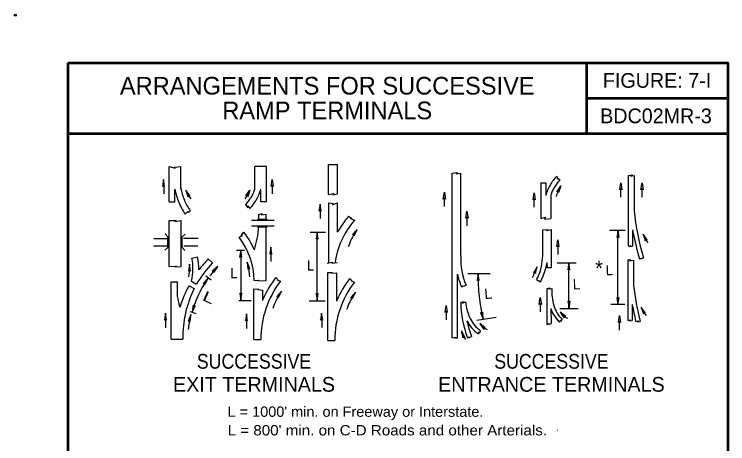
# Model space of a CAD drawing. Extents: x -5.247 to -4.572, y 0.948 to 1.832.
# Drawn here: x -5.247 to -4.616, y 1.452 to 1.832 of the extents above; entities that cross this region are included whole.
import ezdxf
from ezdxf.enums import TextEntityAlignment as Align

# ---------------------------------------------------------------- set-up
doc = ezdxf.new("R2010")
doc.units = 0
doc.header["$LTSCALE"] = 0.0036
doc.header["$PDMODE"] = 32
doc.header["$PDSIZE"] = 0.0018
doc.linetypes.add('LONG_DASHED', pattern=[7.5, 6, -1.5])
doc.linetypes.add('MEDIUM_DASHED', pattern=[4.5, 3, -1.5])
doc.layers.add('1', color=7, linetype='Continuous', lineweight=25)

msp = doc.modelspace()

# ---------------------------------------------------------------- linework, layer by layer
at = {"layer": '1', "lineweight": 53}
for p, q in [((-4.740967, 1.789417), (-4.740967, 1.726917)), ((-4.740967, 1.758167), (-4.615967, 1.758167)), ((-5.1993, 1.726917), (-4.615967, 1.726917))]:
    msp.add_line(p, q, dxfattribs=at)
at = {"layer": '1', "linetype": 'LONG_DASHED'}
for p, q in [((-5.109917, 1.6663), (-5.109917, 1.697758)), ((-5.0995, 1.677425), (-5.0995, 1.697758)), ((-5.023775, 1.697758), (-5.034192, 1.697758)), ((-5.034192, 1.677425), (-5.034192, 1.697758)), ((-5.023775, 1.6663), (-5.023775, 1.697758)), ((-4.781175, 1.683183), (-4.781175, 1.651717)), ((-4.77255, 1.67205), (-4.77255, 1.651717))]:
    msp.add_line(p, q, dxfattribs=at)
at = {"layer": '1'}
for p, q in [((-4.96895, 1.699517), (-4.961067, 1.699517)), ((-4.96895, 1.672733), (-4.96895, 1.699517)), ((-4.961067, 1.673467), (-4.961067, 1.699517)), ((-4.859692, 1.545942), (-4.859692, 1.691775)), ((-4.851883, 1.618633), (-4.851883, 1.691775)), ((-4.704025, 1.689708), (-4.704025, 1.627208)), ((-4.698817, 1.689708), (-4.698817, 1.658458)), ((-5.114783, 1.680583), (-5.114783, 1.673317)), ((-5.018908, 1.680583), (-5.018908, 1.673317)), ((-4.710683, 1.677708), (-4.710683, 1.670442)), ((-4.691875, 1.677708), (-4.691875, 1.670442)), ((-4.866667, 1.669475), (-4.866667, 1.662217)), ((-4.787308, 1.668892), (-4.787308, 1.661633)), ((-4.968658, 1.611975), (-4.968658, 1.665317)), ((-4.961067, 1.639592), (-4.961067, 1.665317)), ((-5.030667, 1.651042), (-5.030708, 1.655192)), ((-5.024275, 1.651025), (-5.024275, 1.655525)), ((-4.976425, 1.658767), (-4.976425, 1.651508)), ((-5.109833, 1.609142), (-5.109833, 1.649858)), ((-5.099417, 1.609142), (-5.099417, 1.649858)), ((-5.037125, 1.650017), (-5.017192, 1.650017)), ((-5.031717, 1.651025), (-5.023283, 1.651025)), ((-4.846675, 1.652425), (-4.846675, 1.645167)), ((-5.037125, 1.645175), (-5.017192, 1.645175)), ((-5.031717, 1.644167), (-5.023283, 1.644167)), ((-5.024275, 1.596758), (-5.024275, 1.644167)), ((-4.779442, 1.623042), (-4.779417, 1.64155)), ((-4.706758, 1.641092), (-4.720592, 1.641092)), ((-4.700208, 1.641483), (-4.700208, 1.627208)), ((-5.111, 1.6353), (-5.11345, 1.638)), ((-5.111, 1.625925), (-5.111, 1.6353)), ((-4.985217, 1.639442), (-4.971567, 1.639442)), ((-5.1137, 1.623475), (-5.111, 1.625925)), ((-5.09595, 1.623225), (-5.0984, 1.625925)), ((-5.050425, 1.623642), (-5.04345, 1.623642)), ((-4.766333, 1.627142), (-4.766333, 1.619883)), ((-5.089842, 1.616608), (-5.084742, 1.61765)), ((-5.075292, 1.615917), (-5.07155, 1.612292)), ((-5.020025, 1.620675), (-5.020025, 1.613417)), ((-4.766767, 1.612333), (-4.749917, 1.612333)), ((-4.704425, 1.615042), (-4.704425, 1.56135)), ((-4.699217, 1.614642), (-4.699217, 1.5926)), ((-4.969592, 1.543667), (-4.969592, 1.603667)), ((-4.961792, 1.5783), (-4.961792, 1.603517)), ((-4.845858, 1.6029), (-4.825942, 1.6029)), ((-5.077408, 1.6008), (-5.07275, 1.597225)), ((-4.8549, 1.545942), (-4.8549, 1.601925)), ((-4.784958, 1.597483), (-4.781558, 1.595683)), ((-5.108208, 1.544917), (-5.108208, 1.5956)), ((-5.092333, 1.592042), (-5.08775, 1.589567)), ((-5.090067, 1.59625), (-5.085633, 1.5935)), ((-5.034983, 1.544525), (-5.034983, 1.589483)), ((-5.027175, 1.579167), (-5.027175, 1.588317)), ((-4.775875, 1.589642), (-4.775925, 1.5579)), ((-5.048383, 1.579167), (-5.037342, 1.579167)), ((-4.986092, 1.578683), (-4.971858, 1.578683)), ((-4.781808, 1.576175), (-4.781808, 1.568917)), ((-4.772542, 1.572067), (-4.772542, 1.572058)), ((-4.772525, 1.571883), (-4.772108, 1.558667)), ((-4.764417, 1.571958), (-4.74835, 1.571958)), ((-4.706958, 1.575433), (-4.719317, 1.575433)), ((-4.7006, 1.575633), (-4.7006, 1.56135)), ((-5.091483, 1.569392), (-5.0864, 1.56755)), ((-4.865092, 1.569125), (-4.865092, 1.561858)), ((-5.113033, 1.56225), (-5.113033, 1.554983)), ((-5.041533, 1.561667), (-5.041533, 1.5544)), ((-4.974983, 1.562392), (-4.974983, 1.555133)), ((-4.837858, 1.561767), (-4.820717, 1.564383)), ((-4.775817, 1.557858), (-4.774217, 1.55865)), ((-4.774267, 1.558725), (-4.774267, 1.557833)), ((-4.774225, 1.557817), (-4.772108, 1.558667)), ((-4.711858, 1.5601), (-4.711858, 1.552842)), ((-5.108208, 1.544917), (-5.097792, 1.544917)), ((-5.034983, 1.544525), (-5.028775, 1.544525)), ((-4.969592, 1.543667), (-4.963383, 1.543667))]:
    msp.add_line(p, q, dxfattribs=at)
at = {"layer": '1', "linetype": 'MEDIUM_DASHED'}
for p, q in [((-4.713025, 1.575433), (-4.713025, 1.640817)), ((-4.978983, 1.578683), (-4.978983, 1.639442)), ((-5.123583, 1.633842), (-5.111567, 1.633842)), ((-5.097275, 1.63405), (-5.0844, 1.63405)), ((-5.1238, 1.627558), (-5.111792, 1.627558)), ((-5.097042, 1.627558), (-5.084617, 1.627558)), ((-5.04665, 1.623642), (-5.0465, 1.57975)), ((-4.756583, 1.571758), (-4.756583, 1.612233))]:
    msp.add_line(p, q, dxfattribs=at)
at = {"layer": '1', "lineweight": 53}
msp.add_lwpolyline([(-5.1993, 1.789417), (-4.615967, 1.789417), (-4.615967, 0.99775), (-5.1993, 0.99775)], close=True, dxfattribs=at)
at = {"layer": '1', "linetype": 'LONG_DASHED'}
for points in [[(-5.109917, 1.697758), (-5.104567, 1.69625), (-5.105, 1.696975), (-5.0995, 1.697758)], [(-4.781175, 1.683183), (-4.776917, 1.683233), (-4.776917, 1.67205)], [(-5.109917, 1.6663), (-5.1048, 1.666233), (-5.1048, 1.677425)], [(-5.023775, 1.6663), (-5.028883, 1.666233), (-5.028883, 1.677425)]]:
    msp.add_lwpolyline(points, dxfattribs=at)
at = {"layer": '1'}
for points in [[(-4.859692, 1.691775), (-4.855017, 1.692417), (-4.856025, 1.6911), (-4.851883, 1.691775)], [(-4.767183, 1.68905), (-4.766425, 1.686425), (-4.766083, 1.687317), (-4.764292, 1.685917)], [(-4.704025, 1.689708), (-4.700292, 1.690208), (-4.701975, 1.688967), (-4.698817, 1.689708)], [(-4.96895, 1.672733), (-4.964608, 1.673733), (-4.965283, 1.672675), (-4.961067, 1.673467)], [(-5.042292, 1.663958), (-5.04045, 1.66105), (-5.04045, 1.66285), (-5.038617, 1.660425)], [(-4.968658, 1.665317), (-4.964583, 1.664733), (-4.965458, 1.663567), (-4.961067, 1.665317)], [(-5.0957, 1.6554), (-5.0935, 1.657667), (-5.0935, 1.656767), (-5.091317, 1.658417)], [(-5.030708, 1.655192), (-5.027567, 1.655983), (-5.028458, 1.654858), (-5.024275, 1.655525)], [(-4.9512, 1.65365), (-4.948342, 1.651458), (-4.949533, 1.651675), (-4.946042, 1.650025)], [(-5.109833, 1.649858), (-5.103617, 1.649733), (-5.104775, 1.649008), (-5.099417, 1.649858)], [(-4.781175, 1.651717), (-4.777108, 1.652758), (-4.778017, 1.651067), (-4.77255, 1.651717)], [(-4.779417, 1.64155), (-4.775425, 1.641725), (-4.7761, 1.640933), (-4.771967, 1.641942)], [(-4.771967, 1.641942), (-4.771967, 1.607833), (-4.7753, 1.607842), (-4.775683, 1.61255)], [(-5.0984, 1.625925), (-5.0984, 1.6353), (-5.0957, 1.63775)], [(-5.048025, 1.634975), (-5.04505, 1.63665), (-5.046358, 1.636508), (-5.043842, 1.639467)], [(-4.704025, 1.627208), (-4.701683, 1.627667), (-4.702525, 1.626875), (-4.700208, 1.627208)], [(-4.693942, 1.615808), (-4.692292, 1.616633), (-4.692733, 1.616008), (-4.690483, 1.6169)], [(-5.109833, 1.609142), (-5.10375, 1.609475), (-5.104917, 1.60875), (-5.099417, 1.609142)], [(-4.970217, 1.611975), (-4.965717, 1.61285), (-4.966158, 1.612125), (-4.961067, 1.612558)], [(-4.704425, 1.615042), (-4.701517, 1.614883), (-4.702858, 1.614267), (-4.699217, 1.614642)], [(-4.969592, 1.603667), (-4.965575, 1.603842), (-4.966008, 1.603108), (-4.961792, 1.603517)], [(-5.034692, 1.596758), (-5.030667, 1.597042), (-5.03125, 1.596458), (-5.024275, 1.596758)], [(-5.015708, 1.599383), (-5.013742, 1.59755), (-5.014383, 1.5974), (-5.011483, 1.596175)], [(-4.950325, 1.598517), (-4.948358, 1.596683), (-4.949, 1.596542), (-4.946092, 1.595308)], [(-5.108208, 1.5956), (-5.102908, 1.5956), (-5.102908, 1.584667)], [(-4.851375, 1.59115), (-4.84985, 1.592108), (-4.849775, 1.591675), (-4.84735, 1.592683)], [(-4.775875, 1.589642), (-4.773217, 1.590133), (-4.774275, 1.588967), (-4.771542, 1.589567)], [(-5.034983, 1.589483), (-5.03095, 1.589192), (-5.031675, 1.588758), (-5.027175, 1.588317)], [(-4.852108, 1.577175), (-4.849633, 1.57805), (-4.850508, 1.576733), (-4.847892, 1.577758)], [(-4.764633, 1.559775), (-4.763625, 1.561525), (-4.76365, 1.560358), (-4.76225, 1.5623)], [(-4.704425, 1.56135), (-4.701933, 1.561792), (-4.702892, 1.561108), (-4.7006, 1.56135)], [(-4.697225, 1.560558), (-4.694958, 1.560942), (-4.695858, 1.560217), (-4.693433, 1.560333)], [(-4.836417, 1.549417), (-4.835683, 1.5513), (-4.835542, 1.550142), (-4.834458, 1.552275)], [(-4.859692, 1.545942), (-4.85705, 1.54665), (-4.857633, 1.545925), (-4.8549, 1.545942)], [(-4.84615, 1.545925), (-4.844692, 1.546942), (-4.84455, 1.546067), (-4.84265, 1.547192)]]:
    msp.add_lwpolyline(points, dxfattribs=at)
for points in [[(-5.1158, 1.679933), (-5.114875, 1.681058), (-5.113958, 1.679933), (-5.114875, 1.6861)], [(-5.017883, 1.679933), (-5.018817, 1.681058), (-5.019733, 1.679933), (-5.018817, 1.6861)], [(-4.765483, 1.674508), (-4.765817, 1.675925), (-4.767133, 1.675317), (-4.763592, 1.680442)], [(-4.709667, 1.677058), (-4.710592, 1.678183), (-4.711508, 1.677058), (-4.710592, 1.683225)], [(-4.69085, 1.677058), (-4.691775, 1.678183), (-4.692692, 1.677058), (-4.691775, 1.683225)], [(-5.093292, 1.670708), (-5.092958, 1.672125), (-5.09165, 1.671517), (-5.095192, 1.676642)], [(-5.0404, 1.670708), (-5.040733, 1.672125), (-5.042042, 1.671517), (-5.0385, 1.676642)], [(-4.865642, 1.668833), (-4.866567, 1.669958), (-4.867483, 1.668833), (-4.866567, 1.675)], [(-4.786292, 1.66825), (-4.787217, 1.669375), (-4.788133, 1.66825), (-4.787217, 1.674417)], [(-4.97745, 1.658125), (-4.976525, 1.65925), (-4.975608, 1.658125), (-4.976525, 1.664292)], [(-4.84565, 1.651775), (-4.846583, 1.6529), (-4.8475, 1.651775), (-4.846583, 1.657942)], [(-4.947825, 1.637342), (-4.94645, 1.637775), (-4.946283, 1.636333), (-4.943708, 1.642008)], [(-4.713892, 1.634808), (-4.712967, 1.635933), (-4.71205, 1.634808), (-4.712967, 1.640975)], [(-4.980042, 1.633258), (-4.979117, 1.634383), (-4.9782, 1.633258), (-4.979117, 1.639425)], [(-4.688983, 1.631892), (-4.68865, 1.633308), (-4.687342, 1.632708), (-4.690883, 1.637833)], [(-4.765308, 1.6265), (-4.766233, 1.627625), (-4.76715, 1.6265), (-4.766233, 1.632667)], [(-5.047617, 1.617267), (-5.046692, 1.618392), (-5.045775, 1.617267), (-5.046692, 1.623433)], [(-5.021042, 1.620025), (-5.020117, 1.62115), (-5.0192, 1.620025), (-5.020117, 1.626192)], [(-5.092925, 1.604942), (-5.092, 1.606067), (-5.091083, 1.604942), (-5.092, 1.611108)], [(-5.071783, 1.605), (-5.070342, 1.605233), (-5.0704, 1.603792), (-5.067033, 1.609042)], [(-5.040325, 1.606667), (-5.039733, 1.608), (-5.038542, 1.60715), (-5.04105, 1.612858)], [(-4.787642, 1.603475), (-4.786375, 1.604192), (-4.785925, 1.602817), (-4.784567, 1.6089)], [(-4.7575, 1.606133), (-4.756567, 1.607258), (-4.75565, 1.606133), (-4.756567, 1.6123)], [(-4.837667, 1.596767), (-4.836733, 1.597892), (-4.835817, 1.596767), (-4.836733, 1.602933)], [(-5.07975, 1.594142), (-5.078358, 1.594542), (-5.078242, 1.593092), (-5.075492, 1.598683)], [(-5.045658, 1.5854), (-5.046575, 1.584275), (-5.0475, 1.5854), (-5.046575, 1.579225)], [(-5.014667, 1.582675), (-5.013292, 1.583108), (-5.013125, 1.581667), (-5.01055, 1.587342)], [(-4.978083, 1.585175), (-4.979, 1.58405), (-4.979925, 1.585175), (-4.979, 1.579)], [(-4.949283, 1.581808), (-4.947908, 1.58225), (-4.947742, 1.5808), (-4.945167, 1.586475)], [(-4.780792, 1.575525), (-4.781717, 1.57665), (-4.782633, 1.575525), (-4.781717, 1.581692)], [(-4.7554, 1.578417), (-4.756317, 1.577292), (-4.75725, 1.578417), (-4.756317, 1.572233)], [(-4.7121, 1.58165), (-4.713017, 1.580525), (-4.713942, 1.58165), (-4.713017, 1.575475)], [(-5.0869, 1.574333), (-5.088108, 1.573525), (-5.088658, 1.574883), (-5.089617, 1.568708)], [(-4.864067, 1.568475), (-4.865, 1.5696), (-4.865917, 1.568475), (-4.865, 1.574642)], [(-4.690558, 1.567217), (-4.690225, 1.568633), (-4.688917, 1.568025), (-4.692458, 1.57315)], [(-5.11405, 1.5616), (-5.113125, 1.562725), (-5.112208, 1.5616), (-5.113125, 1.567767)], [(-5.093025, 1.560858), (-5.091883, 1.561775), (-5.091208, 1.560483), (-5.090883, 1.566725)], [(-5.04255, 1.561017), (-5.041625, 1.562142), (-5.040708, 1.561017), (-5.041625, 1.567183)], [(-4.976, 1.56175), (-4.975075, 1.562875), (-4.974158, 1.56175), (-4.975075, 1.567917)], [(-4.832683, 1.568833), (-4.833308, 1.567517), (-4.834475, 1.568392), (-4.832108, 1.562608)], [(-4.7606, 1.563625), (-4.760692, 1.565067), (-4.759258, 1.564883), (-4.764142, 1.56875)], [(-4.710842, 1.559458), (-4.711767, 1.560583), (-4.712683, 1.559458), (-4.711767, 1.565625)], [(-4.831717, 1.553483), (-4.831808, 1.554933), (-4.830375, 1.55475), (-4.835258, 1.558608)], [(-4.850292, 1.546067), (-4.8498, 1.547442), (-4.848558, 1.546708), (-4.851517, 1.552183)]]:
    msp.add_lwpolyline(points, close=True, dxfattribs=at)
at = {"layer": '1', "linetype": 'LONG_DASHED'}
for centre, radius, start, end in [((-4.738039, 1.661085), 0.04039, 136.18456, 164.25009), ((-4.738445, 1.661116), 0.035811, 136.18456, 162.22057), ((-5.04846, 1.687824), 0.05198, 190.45958, 214.46417), ((-5.04846, 1.687824), 0.057294, 190.45958, 214.46417), ((-5.067759, 1.688386), 0.035296, 316.18456, 342.22057), ((-5.067759, 1.688386), 0.04039, 316.18456, 344.25009)]:
    msp.add_arc(centre, radius, start, end, dxfattribs=at)
at = {"layer": '1'}
for centre, radius, start, end in [((-5.065929, 1.688386), 0.031536, 203.52741, 217.63846), ((-5.067759, 1.688386), 0.031536, 322.36154, 336.47259), ((-4.753822, 1.668205), 0.014244, 145.63153, 168.44423), ((-4.891714, 1.602331), 0.07856, 139.21513, 151.54986), ((-4.467588, 1.683193), 0.232551, 186.10667, 196.56205), ((-4.891714, 1.602331), 0.072289, 138.71884, 171.61107), ((-5.113829, 1.649053), 0.083179, 342.33247, 356.60516), ((-4.467588, 1.683193), 0.236169, 190.14614, 196.5786), ((-5.100964, 1.595074), 0.066297, 1.45372, 37.00075), ((-5.100964, 1.595074), 0.072343, 23.40545, 37.85492), ((-4.876386, 1.59903), 0.080084, 149.28096, 159.77954), ((-4.661622, 1.649574), 0.031536, 203.52741, 217.63846), ((-4.847568, 1.622622), 0.068159, 344.42229, 0.59411), ((-5.137298, 1.606937), 0.04843, 347.24704, 11.5221), ((-5.137298, 1.606937), 0.053638, 359.10991, 11.5221), ((-5.004579, 1.547407), 0.098454, 135.90934, 143.24436), ((-4.798907, 1.614502), 0.053135, 175.54312, 204.24728), ((-5.137298, 1.606937), 0.045416, 351.23537, 2.95648), ((-5.004579, 1.547407), 0.093246, 135.90934, 150.37611), ((-5.100964, 1.595074), 0.062655, 4.39028, 13.72325), ((-4.833693, 1.623301), 0.058998, 332.08843, 349.49866), ((-5.004579, 1.547407), 0.087556, 135.57503, 142.38249), ((-4.833693, 1.623301), 0.050919, 332.08843, 340.54605), ((-4.833693, 1.623301), 0.055159, 332.08843, 340.54605), ((-4.943229, 1.544363), 0.090997, 142.79701, 157.02765), ((-4.877844, 1.543498), 0.090997, 142.79701, 157.02765), ((-4.798907, 1.614502), 0.057425, 192.22771, 203.98762), ((-5.006614, 1.543614), 0.098454, 150.53978, 162.50107), ((-4.943229, 1.544363), 0.085687, 142.79701, 179.95983), ((-4.877844, 1.543498), 0.085687, 142.79701, 179.95983), ((-4.467984, 1.617339), 0.232551, 186.10667, 194.19105), ((-5.05428, 1.589042), 0.048865, 185.00766, 198.89969), ((-5.004579, 1.547407), 0.093246, 153.1182, 181.53322), ((-4.943229, 1.544363), 0.080084, 149.28096, 159.77954), ((-4.877844, 1.543498), 0.080084, 149.28096, 159.77954), ((-4.728021, 1.587323), 0.043575, 177.04583, 196.99701), ((-4.804559, 1.582346), 0.043575, 186.04583, 205.99701), ((-4.753001, 1.579877), 0.099146, 181.56268, 200.02697), ((-4.743812, 1.581849), 0.030343, 199.1, 226.66746), ((-4.743812, 1.581849), 0.026876, 195.67603, 226.66746), ((-4.467984, 1.617339), 0.236169, 190.17069, 193.9119), ((-4.663195, 1.584897), 0.031536, 203.52741, 217.63846), ((-5.005819, 1.545501), 0.087556, 167.06934, 174.84091), ((-4.75207, 1.577089), 0.014744, 214.75549, 248.27566), ((-4.753001, 1.579877), 0.095423, 191.31281, 200.02697), ((-4.819299, 1.574469), 0.030343, 206.0103, 235.66746), ((-4.819299, 1.574469), 0.026876, 204.67603, 235.66746), ((-4.823184, 1.566953), 0.014744, 214.75549, 248.27566), ((-4.822779, 1.56373), 0.031536, 203.52741, 217.63846)]:
    msp.add_arc(centre, radius, start, end, dxfattribs=at)
at = {"layer": '1', "linetype": 'MEDIUM_DASHED'}
for centre, radius, start, end in [((-4.69133, 1.599055), 0.145421, 178.54145, 194.38233), ((-5.004579, 1.547407), 0.087556, 143.85806, 165.80304)]:
    msp.add_arc(centre, radius, start, end, dxfattribs=at)
at = {"layer": '1'}
msp.add_point((-5.246008, 1.831442), dxfattribs=at)

# ---------------------------------------------------------------- texts
for s, height, p in [('FIGURE: 7-I', 0.01303, (-4.678467, 1.767275)), ('ARRANGEMENTS FOR SUCCESSIVE', 0.01562, (-4.970129, 1.761292)), ('RAMP TERMINALS', 0.01562, (-4.970133, 1.739417)), ('BDC02MR-3', 0.01303, (-4.679421, 1.735917)), ('EXIT TERMINALS', 0.01303, (-5.034896, 1.498308)), ('ENTRANCE TERMINALS', 0.01303, (-4.7719, 1.498308))]:
    msp.add_text(s, height=height, dxfattribs=at).set_placement(p, align=Align.CENTER)
at = {"layer": '1', "width": 0.9}
for s, height, p in [('L', 0.009117, (-4.984967, 1.605492)), ('L', 0.009117, (-5.052658, 1.598758)), ('SUCCESSIVE', 0.01303, (-5.034904, 1.518683)), ('SUCCESSIVE', 0.01303, (-4.771904, 1.518683)), ('.', 0.00651, (-4.766625, 1.463692))]:
    msp.add_text(s, height=height, dxfattribs=at).set_placement(p, align=Align.CENTER)
at = {"layer": '1'}
msp.add_text('*', height=0.01335, dxfattribs=at).set_placement((-4.733217, 1.600917))
for rotation, width, p in [(1.881, 0.95, (-4.720554, 1.601397)), (1.881, 0.95, (-4.749554, 1.588855)), (335.36, 1.5, (-5.076775, 1.577544))]:
    msp.add_text('L', height=0.009117, rotation=rotation, dxfattribs=dict(at, width=width)).set_placement(p, align=Align.CENTER)
msp.add_text('L', height=0.009117, rotation=4.687, dxfattribs=at).set_placement((-4.82746, 1.580531), align=Align.CENTER)
for s, width, p in [("L = 1000' min. on Freeway or Interstate.", 1.05, (-5.05825, 1.476108)), ("L = 800' min. on C-D Roads and other Arterials.", 1.1, (-5.05825, 1.459642))]:
    msp.add_text(s, height=0.009117, dxfattribs=dict(at, width=width)).set_placement(p)

doc.saveas('drawing.dxf')
